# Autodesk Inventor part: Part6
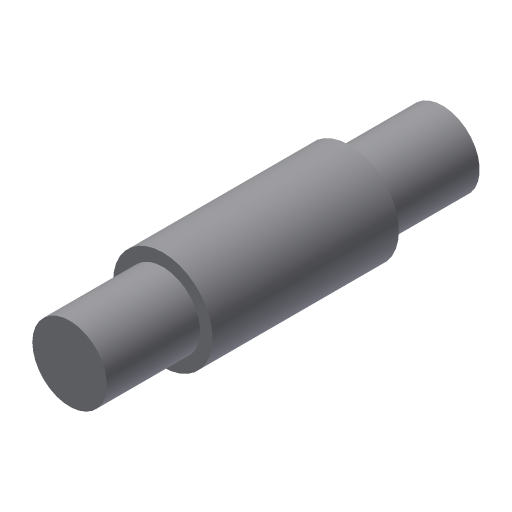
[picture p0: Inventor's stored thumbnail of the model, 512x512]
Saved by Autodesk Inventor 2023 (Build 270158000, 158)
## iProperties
Created: 2002-01
Part Number: Part6
Document SubType Name: Modeling
Designer: ***
Density: 1 g/cm^3
Material: Generic
Appearance: Default
Control State: 0
Master: False
Checked Out: False
Shininess: 77.0
Length Units: 11269
Angle Units: 11279
Time Units: 11290
Mass Units: 11283
Length Display Precision: 3
Angle Display Precision: 2
Density: 0.0
Volumn: 0.0
Area: 0.0
PropertySet Name: Model Information
Author: ***
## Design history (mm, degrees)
sketch "Sketch1"
  geometry: L1 (1.545, 32.521)-(-4.455, 32.521); L2 (-4.455, 32.521)-(-4.455, 17.521); L3 (-4.455, 17.521)-(-6.455, 17.521); L4 (-6.455, 17.521)-(-6.455, -12.479); L5 (-6.455, -12.479)-(-4.455, -12.479); L6 (-4.455, -12.479)-(-4.455, -27.479); L7 (-4.455, -27.479)-(1.545, -27.479); L8 (1.545, -27.479)-(1.545, 32.521)
  constraints: 16 end point, 5 parallel, 2 equal length, 1 collinear, 1 horizontal, 1 perpendicular
  dimensions: "d0" = 16 diameter of L4 L8; "d1" = 12 diameter of L2 L8; "d2" = 60 distance of L7.end L1.start; "d3" = 30 distance of L3.end L4.end
revolve "Revolution1" sketch "Sketch1" stored, may be unused: angle "d4" = 90 deg
body "Solid1"
